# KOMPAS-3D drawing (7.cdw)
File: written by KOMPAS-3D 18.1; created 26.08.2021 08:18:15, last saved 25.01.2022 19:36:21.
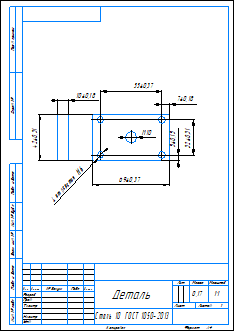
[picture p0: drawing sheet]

Sheet 1: A4, portrait

Document properties: Автор: 111; Масса: 0.170089; Полное имя файла: 2.m3d

Title block, sheet 1: Наименование: Деталь; Материал: Сталь 10  ГОСТ 1050-2013; Масса: 0,17; Количество листов документа: 1; Форматы листов документа: A4; stored path: C:\Users\admin\Desktop\ffb\7.cdw

Dimensions and other numbers on the sheet: 55±0,37; 7±0,18; 32±0,31; 5±0,15; 42±0,31; 69±0,37; 10±0,18; 4 отверстия; 6; 1:1; 1; 0,17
